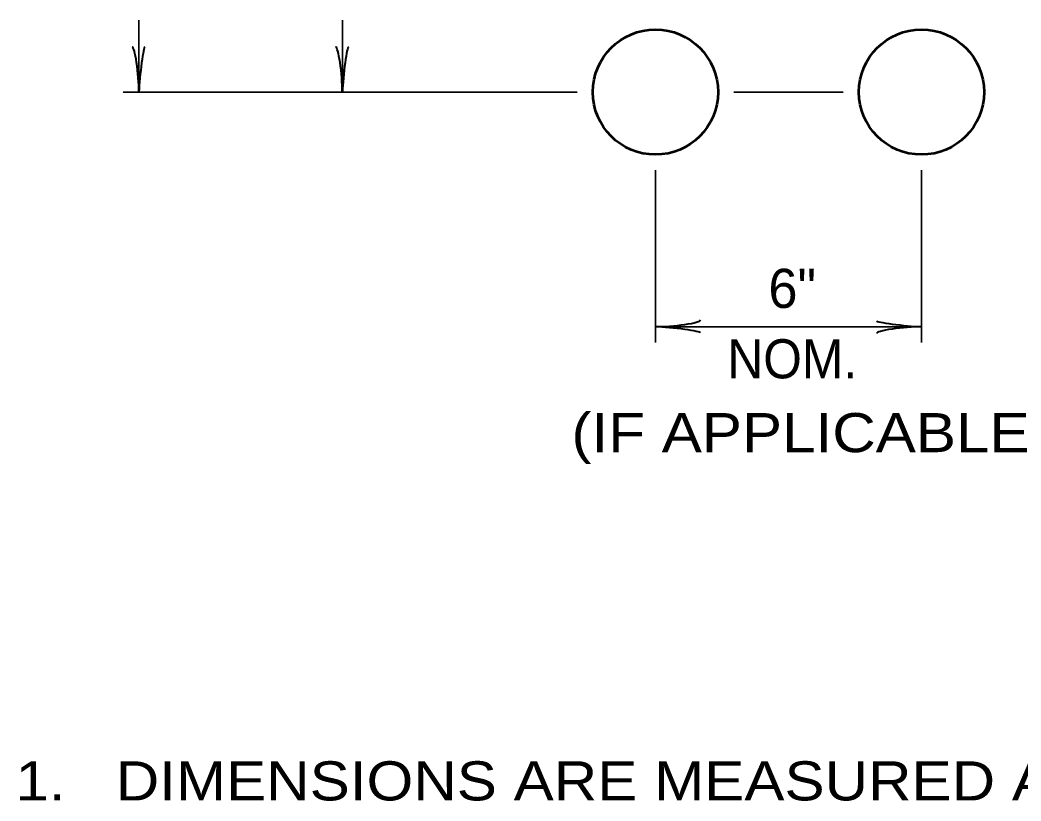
# Model space of a CAD drawing. Extents: x -1 to 679, y 0 to 440.
# Drawn here: x 326.9 to 390.8, y 94.9 to 144.8 of the extents above; entities that cross this region are included whole.
import ezdxf
from ezdxf.enums import TextEntityAlignment as Align

# ---------------------------------------------------------------- set-up
doc = ezdxf.new("R2010")
doc.units = 0
doc.layers.add('1', color=7, linetype='Continuous', lineweight=35)

msp = doc.modelspace()

# ---------------------------------------------------------------- linework, layer by layer
at = {"layer": '1'}
for p, q in [((334.484, 140.189), (334.484, 144.793)), ((347.484, 140.189), (347.484, 144.793)), ((362.484, 140.189), (333.484, 140.189)), ((372.484, 140.189), (379.484, 140.189)), ((367.484, 135.19), (367.484, 124.189)), ((384.484, 135.19), (384.484, 124.189)), ((367.484, 125.189), (384.484, 125.189))]:
    msp.add_line(p, q, dxfattribs=at)
at = {"layer": '1', "lineweight": 53}
for centre in [(367.484, 140.189), (384.484, 140.189)]:
    msp.add_circle(centre, 4, dxfattribs=at)
at = {"layer": '1', "lineweight": 40}
for centre, major_axis, ratio, start_param, end_param in [((334.208, 141.281), (0.156, -1.786), 0.122415, 0.896353, 3.141593), ((334.208, 141.281), (0.156, -1.786), 0.122415, 0.896353, 3.141593), ((334.696, 141.31), (-0.176, -1.756), 0.07063, 3.140715, 5.41811), ((334.696, 141.31), (-0.176, -1.756), 0.07063, 3.140715, 5.41811), ((347.208, 141.281), (0.156, -1.786), 0.122415, 0.896353, 3.141593), ((347.208, 141.281), (0.156, -1.786), 0.122415, 0.896353, 3.141593), ((347.696, 141.31), (-0.176, -1.756), 0.07063, 3.140715, 5.41811), ((347.696, 141.31), (-0.176, -1.756), 0.07063, 3.140715, 5.41811), ((368.576, 125.466), (-1.786, -0.156), 0.122415, 0.896353, 3.141593), ((368.576, 125.466), (-1.786, -0.156), 0.122415, 0.896353, 3.141593), ((383.364, 125.401), (1.756, -0.176), 0.07063, 3.140715, 5.41811), ((368.605, 124.978), (-1.756, 0.176), 0.07063, 3.140715, 5.41811), ((368.605, 124.978), (-1.756, 0.176), 0.07063, 3.140715, 5.41811), ((383.393, 124.913), (1.786, 0.156), 0.122415, 0.896353, 3.141593)]:
    msp.add_ellipse(centre, major_axis=major_axis, ratio=ratio, start_param=start_param, end_param=end_param, dxfattribs=at)

# ---------------------------------------------------------------- texts
at = {"layer": '1'}
msp.add_text('6"', height=2.5, dxfattribs=at).set_placement((376.226, 126.393), align=Align.CENTER)
at = {"layer": '1', "width": 0.95}
msp.add_text('NOM.', height=2.5, dxfattribs=at).set_placement((376.226, 121.893), align=Align.CENTER)
at = {"layer": '1', "width": 1.15}
for s, p in [('(IF APPLICABLE)', (362.121, 117.174)), ('1.   DIMENSIONS ARE MEASURED AT POINT OF CONDUIT', (326.596, 94.919))]:
    msp.add_text(s, height=2.5, dxfattribs=at).set_placement(p)

doc.saveas('drawing.dxf')
